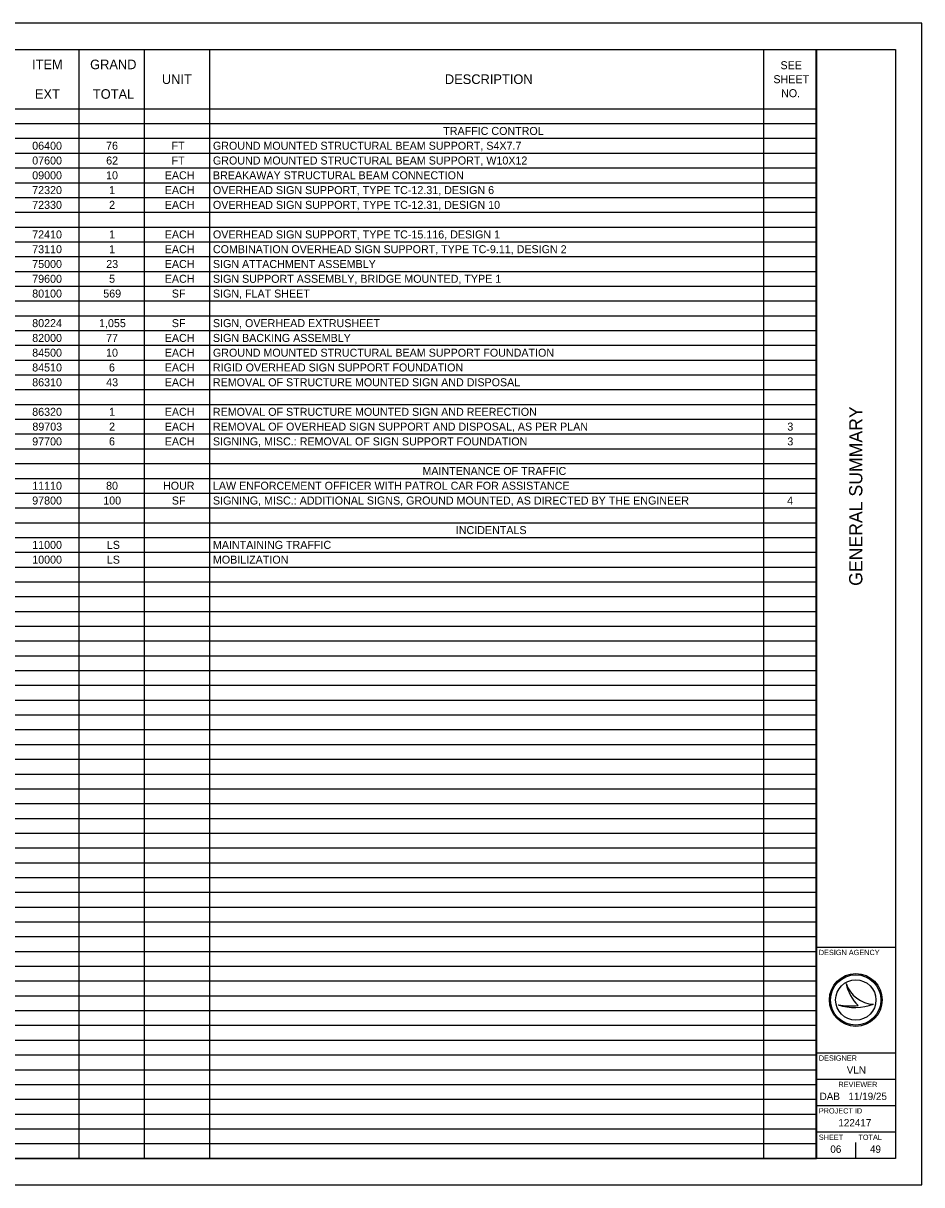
# Model space of a CAD drawing. Extents: x 0 to 34, y 0 to 22.
# Drawn here: x 16.98 to 34, y 0 to 22 of the extents above; entities that cross this region are included whole.
import ezdxf

# ---------------------------------------------------------------- set-up
doc = ezdxf.new("R2010")
doc.units = 0
for name, color, linetype in [('SH_Border', 7, 'Continuous'), ('SH_Cut_Line', 7, 'Continuous'), ('SH_Data', 7, 'Continuous'), ('SH_Text', 7, 'Continuous')]:
    doc.layers.add(name, color=color, linetype=linetype)

msp = doc.modelspace()

# ---------------------------------------------------------------- linework, layer by layer
at = {"layer": 'SH_Border'}
for p, q in [((32, 0.5), (32, 21.5)), ((32, 4.5), (33.5, 4.5)), ((32, 2.5), (33.5, 2.5)), ((32, 2), (33.5, 2)), ((32, 1.5), (33.5, 1.5)), ((32, 1), (33.5, 1))]:
    msp.add_line(p, q, dxfattribs=at)
msp.add_lwpolyline([(1.5, 21.5), (33.5, 21.5), (33.5, 0.5), (1.5, 0.5)], close=True, dxfattribs=at)
at = {"layer": 'SH_Cut_Line'}
msp.add_lwpolyline([(0, 0), (34, 0), (34, 22), (0, 22)], close=True, dxfattribs=at)
at = {"layer": 'SH_Data'}
for p, q in [((32.567, 3.81), (32.567, 3.81)), ((32.417, 3.41), (32.417, 3.41)), ((32.75, 3.5), (32.75, 3.5)), ((33.087, 3.419), (33.087, 3.419)), ((32.375, 0.675), (32.375, 0.675)), ((32.75, 0.5), (32.75, 0.8))]:
    msp.add_line(p, q, dxfattribs=at)
for radius in [0.5, 0.477, 0.477, 0.382]:
    msp.add_circle((32.75, 3.5), radius, dxfattribs=at)
for centre, radius, start, end in [((33.116, 3.998), 0.58, 198.9257, 198.9319), ((33.347, 3.97), 0.796, 191.6379, 191.6421), ((33.116, 3.998), 0.58, 198.9319, 267.1657), ((33.347, 3.97), 0.796, 191.6421, 226.0947), ((32.739, 4.37), 1.013, 251.4576, 290.0832), ((32.648, 4.654), 1.266, 259.4964, 259.4995), ((32.739, 4.37), 1.013, 251.4527, 251.4576), ((32.648, 4.654), 1.266, 259.4995, 276.6672)]:
    msp.add_arc(centre, radius, start, end, dxfattribs=at)
at = {"layer": 'SH_Text'}
for p, q in [((1.5, 21.5), (32.004, 21.5)), ((18.036, 21.5), (18.036, 0.5)), ((19.272, 21.5), (19.272, 0.5)), ((20.507, 21.5), (20.507, 0.5)), ((30.999, 21.5), (30.999, 0.5)), ((32.004, 21.5), (32.004, 0.5)), ((1.5, 20.38), (32.004, 20.38)), ((1.5, 20.1), (32.004, 20.1)), ((1.5, 19.82), (32.004, 19.82)), ((1.5, 19.54), (32.004, 19.54)), ((1.5, 19.26), (32.004, 19.26)), ((1.5, 18.98), (32.004, 18.98)), ((1.5, 18.7), (32.004, 18.7)), ((1.5, 18.42), (32.004, 18.42)), ((1.5, 18.14), (32.004, 18.14)), ((1.5, 17.86), (32.004, 17.86)), ((1.5, 17.58), (32.004, 17.58)), ((1.5, 17.3), (32.004, 17.3)), ((1.5, 17.02), (32.004, 17.02)), ((1.5, 16.74), (32.004, 16.74)), ((1.5, 16.46), (32.004, 16.46)), ((1.5, 16.18), (32.004, 16.18)), ((1.5, 15.9), (32.004, 15.9)), ((1.5, 15.62), (32.004, 15.62)), ((1.5, 15.34), (32.004, 15.34)), ((1.5, 15.06), (32.004, 15.06)), ((1.5, 14.78), (32.004, 14.78)), ((1.5, 14.5), (32.004, 14.5)), ((1.5, 14.22), (32.004, 14.22)), ((1.5, 13.94), (32.004, 13.94)), ((1.5, 13.66), (32.004, 13.66)), ((1.5, 13.38), (32.004, 13.38)), ((1.5, 13.1), (32.004, 13.1)), ((1.5, 12.82), (32.004, 12.82)), ((1.5, 12.54), (32.004, 12.54)), ((1.5, 12.26), (32.004, 12.26)), ((1.5, 11.98), (32.004, 11.98)), ((1.5, 11.7), (32.004, 11.7)), ((1.5, 11.42), (32.004, 11.42)), ((1.5, 11.14), (32.004, 11.14)), ((1.5, 10.86), (32.004, 10.86)), ((1.5, 10.58), (32.004, 10.58)), ((1.5, 10.3), (32.004, 10.3)), ((1.5, 10.02), (32.004, 10.02)), ((1.5, 9.74), (32.004, 9.74)), ((1.5, 9.46), (32.004, 9.46)), ((1.5, 9.18), (32.004, 9.18)), ((1.5, 8.9), (32.004, 8.9)), ((1.5, 8.62), (32.004, 8.62)), ((1.5, 8.34), (32.004, 8.34)), ((1.5, 8.06), (32.004, 8.06)), ((1.5, 7.78), (32.004, 7.78)), ((1.5, 7.5), (32.004, 7.5)), ((1.5, 7.22), (32.004, 7.22)), ((1.5, 6.94), (32.004, 6.94)), ((1.5, 6.66), (32.004, 6.66)), ((1.5, 6.38), (32.004, 6.38)), ((1.5, 6.1), (32.004, 6.1)), ((1.5, 5.82), (32.004, 5.82)), ((1.5, 5.54), (32.004, 5.54)), ((1.5, 5.26), (32.004, 5.26)), ((1.5, 4.98), (32.004, 4.98)), ((1.5, 4.7), (32.004, 4.7)), ((1.5, 4.42), (32.004, 4.42)), ((1.5, 4.14), (32.004, 4.14)), ((1.5, 3.86), (32.004, 3.86)), ((1.5, 3.58), (32.004, 3.58)), ((1.5, 3.3), (32.004, 3.3)), ((1.5, 3.02), (32.004, 3.02)), ((1.5, 2.74), (32.004, 2.74)), ((1.5, 2.46), (32.004, 2.46)), ((1.5, 2.18), (32.004, 2.18)), ((1.5, 1.9), (32.004, 1.9)), ((1.5, 1.62), (32.004, 1.62)), ((1.5, 1.34), (32.004, 1.34)), ((1.5, 1.06), (32.004, 1.06)), ((1.5, 0.78), (32.004, 0.78)), ((1.5, 0.5), (32.004, 0.5))]:
    msp.add_line(p, q, dxfattribs=at)

# ---------------------------------------------------------------- texts
at = {"layer": 'SH_Data'}
msp.add_text('GENERAL SUMMARY', height=0.25, rotation=90, dxfattribs=at).set_placement((32.875, 11.344))
for s, height, p in [('DESIGN AGENCY', 0.1, (32.05, 4.35)), ('DESIGNER', 0.1, (32.05, 2.35)), ('VLN', 0.14, (32.579, 2.105)), ('REVIEWER', 0.1, (32.422, 1.85)), ('DAB', 0.14, (32.065, 1.605)), ('11/19/25', 0.14, (32.611, 1.605)), ('PROJECT ID', 0.1, (32.05, 1.35)), ('122417', 0.14, (32.42, 1.105)), ('SHEET', 0.1, (32.05, 0.85)), ('TOTAL', 0.1, (32.8, 0.85)), ('06', 0.14, (32.268, 0.605)), ('49', 0.14, (33.019, 0.605))]:
    msp.add_text(s, height=height, dxfattribs=at).set_placement(p)
at = {"layer": 'SH_Text'}
for s, height, p in [('ITEM', 0.1818, (17.147, 21.129)), ('GRAND', 0.1818, (18.247, 21.129)), ('SEE ', 0.1515, (31.324, 21.129)), ('UNIT', 0.1818, (19.606, 20.849)), ('DESCRIPTION', 0.18184, (24.967, 20.849)), ('SHEET ', 0.1515, (31.19, 20.864)), ('EXT', 0.1818, (17.201, 20.569)), ('TOTAL', 0.1818, (18.299, 20.569)), ('NO.', 0.1515, (31.335, 20.599)), ('TRAFFIC CONTROL', 0.15153, (24.936, 19.884)), ('06400', 0.1515, (17.15, 19.604)), ('76', 0.1515, (18.549, 19.604)), ('FT', 0.1515, (19.789, 19.604)), ('GROUND MOUNTED STRUCTURAL BEAM SUPPORT, S4X7.7', 0.15153, (20.573, 19.604)), ('07600', 0.1515, (17.15, 19.324)), ('62', 0.1515, (18.551, 19.324)), ('FT', 0.1515, (19.789, 19.324)), ('GROUND MOUNTED STRUCTURAL BEAM SUPPORT, W10X12', 0.15153, (20.573, 19.324)), ('09000', 0.1515, (17.15, 19.044)), ('10', 0.1515, (18.549, 19.044)), ('EACH', 0.1515, (19.661, 19.044)), ('BREAKAWAY STRUCTURAL BEAM CONNECTION', 0.15153, (20.573, 19.044)), ('72320', 0.1515, (17.15, 18.764)), ('1', 0.152, (18.606, 18.764)), ('EACH', 0.1515, (19.661, 18.764)), ('OVERHEAD SIGN SUPPORT, TYPE TC-12.31, DESIGN 6', 0.15153, (20.573, 18.764)), ('72330', 0.1515, (17.15, 18.484)), ('2', 0.152, (18.606, 18.484)), ('EACH', 0.1515, (19.661, 18.484)), ('OVERHEAD SIGN SUPPORT, TYPE TC-12.31, DESIGN 10', 0.15153, (20.573, 18.484)), ('72410', 0.1515, (17.15, 17.924)), ('1', 0.152, (18.606, 17.924)), ('EACH', 0.1515, (19.661, 17.924)), ('OVERHEAD SIGN SUPPORT, TYPE TC-15.116, DESIGN 1', 0.15153, (20.573, 17.924)), ('73110', 0.1515, (17.15, 17.644)), ('1', 0.152, (18.606, 17.644)), ('EACH', 0.1515, (19.661, 17.644)), ('COMBINATION OVERHEAD SIGN SUPPORT, TYPE TC-9.11, DESIGN 2', 0.15153, (20.573, 17.644)), ('75000', 0.1515, (17.15, 17.364)), ('23', 0.1515, (18.552, 17.364)), ('EACH', 0.1515, (19.661, 17.364)), ('SIGN ATTACHMENT ASSEMBLY', 0.15153, (20.573, 17.364)), ('79600', 0.1515, (17.15, 17.084)), ('5', 0.152, (18.606, 17.084)), ('EACH', 0.1515, (19.661, 17.084)), ('SIGN SUPPORT ASSEMBLY, BRIDGE MOUNTED, TYPE 1', 0.15153, (20.573, 17.084)), ('80100', 0.1515, (17.15, 16.804)), ('569', 0.1515, (18.496, 16.804)), ('SF', 0.1515, (19.795, 16.804)), ('SIGN, FLAT SHEET', 0.15153, (20.573, 16.804)), ('80224', 0.1515, (17.15, 16.244)), ('1,055', 0.1515, (18.416, 16.244)), ('SF', 0.1515, (19.795, 16.244)), ('SIGN, OVERHEAD EXTRUSHEET', 0.15153, (20.573, 16.244)), ('82000', 0.1515, (17.15, 15.964)), ('77', 0.1515, (18.55, 15.964)), ('EACH', 0.1515, (19.661, 15.964)), ('SIGN BACKING ASSEMBLY', 0.15153, (20.573, 15.964)), ('84500', 0.1515, (17.15, 15.684)), ('10', 0.1515, (18.549, 15.684)), ('EACH', 0.1515, (19.661, 15.684)), ('GROUND MOUNTED STRUCTURAL BEAM SUPPORT FOUNDATION', 0.15153, (20.573, 15.684)), ('84510', 0.1515, (17.15, 15.404)), ('6', 0.152, (18.604, 15.404)), ('EACH', 0.1515, (19.661, 15.404)), ('RIGID OVERHEAD SIGN SUPPORT FOUNDATION', 0.15153, (20.573, 15.404)), ('86310', 0.1515, (17.15, 15.124)), ('43', 0.1515, (18.552, 15.124)), ('EACH', 0.1515, (19.661, 15.124)), ('REMOVAL OF STRUCTURE MOUNTED SIGN AND DISPOSAL', 0.15153, (20.573, 15.124)), ('86320', 0.1515, (17.15, 14.564)), ('1', 0.152, (18.606, 14.564)), ('EACH', 0.1515, (19.661, 14.564)), ('REMOVAL OF STRUCTURE MOUNTED SIGN AND REERECTION', 0.15153, (20.573, 14.564)), ('89703', 0.1515, (17.153, 14.284)), ('2', 0.152, (18.606, 14.284)), ('EACH', 0.1515, (19.661, 14.284)), ('REMOVAL OF OVERHEAD SIGN SUPPORT AND DISPOSAL, AS PER PLAN', 0.15153, (20.573, 14.284)), ('3', 0.152, (31.453, 14.284)), ('97700', 0.1515, (17.15, 14.004)), ('6', 0.152, (18.604, 14.004)), ('EACH', 0.1515, (19.661, 14.004)), ('SIGNING, MISC.: REMOVAL OF SIGN SUPPORT FOUNDATION', 0.15153, (20.573, 14.004)), ('3', 0.152, (31.453, 14.004)), ('MAINTENANCE OF TRAFFIC', 0.15153, (24.542, 13.444)), ('11110', 0.1515, (17.15, 13.164)), ('80', 0.1515, (18.549, 13.164)), ('HOUR', 0.1515, (19.628, 13.164)), ('LAW ENFORCEMENT OFFICER WITH PATROL CAR FOR ASSISTANCE', 0.15153, (20.573, 13.164)), ('97800', 0.1515, (17.15, 12.884)), ('100', 0.1515, (18.495, 12.884)), ('SF', 0.1515, (19.795, 12.884)), ('SIGNING, MISC.: ADDITIONAL SIGNS, GROUND MOUNTED, AS DIRECTED BY THE ENGINEER', 0.15153, (20.573, 12.884)), ('4', 0.152, (31.45, 12.884)), ('INCIDENTALS', 0.15153, (25.174, 12.324)), ('11000', 0.1515, (17.15, 12.044)), ('LS', 0.1515, (18.564, 12.044)), ('MAINTAINING TRAFFIC', 0.15153, (20.573, 12.044)), ('10000', 0.1515, (17.15, 11.764)), ('LS', 0.1515, (18.564, 11.764)), ('MOBILIZATION', 0.15153, (20.573, 11.764))]:
    msp.add_text(s, height=height, dxfattribs=at).set_placement(p)

doc.saveas('drawing.dxf')
